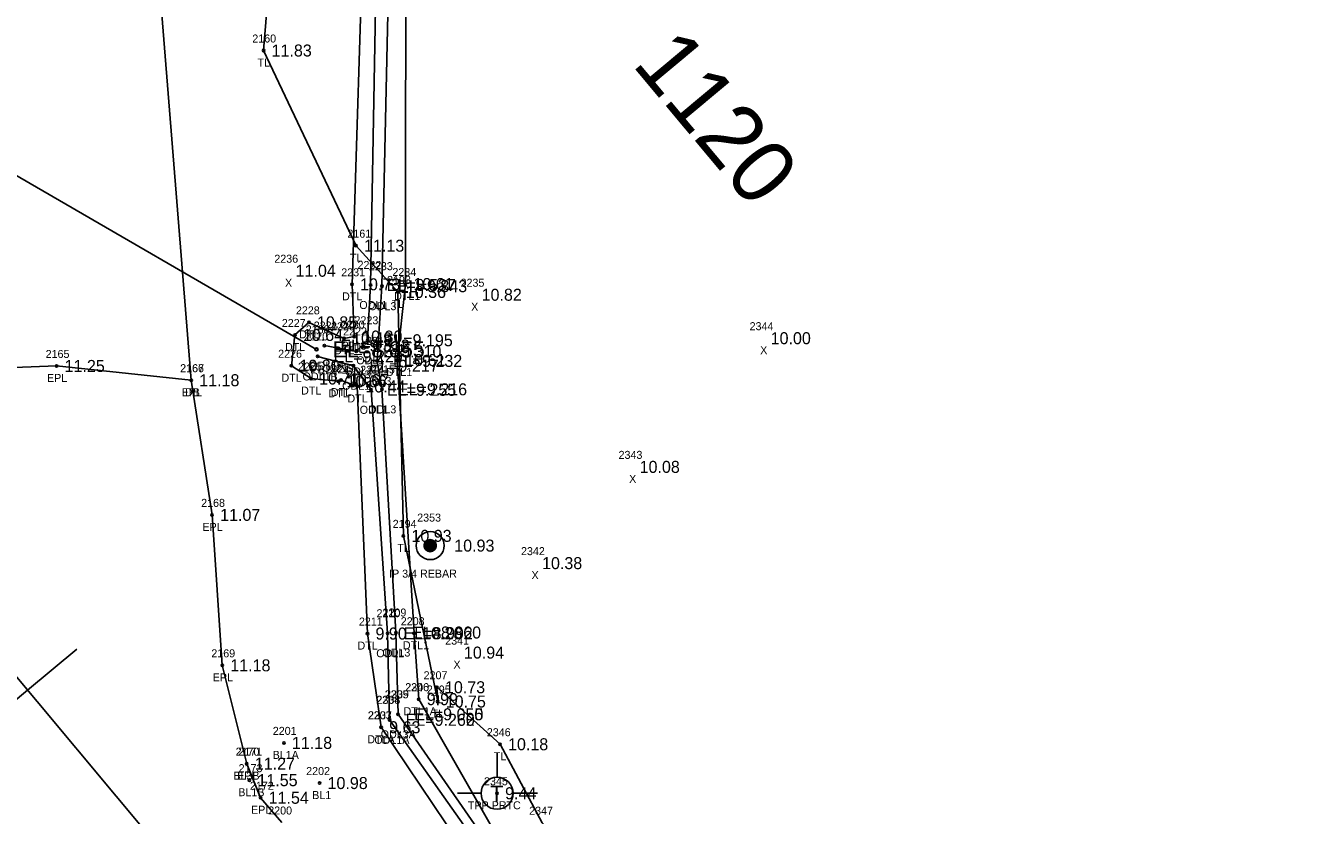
# Model space of a CAD drawing. Extents: x 2042117 to 2045853, y 303080 to 309569.
# Drawn here: x 2044366.1 to 2044524.3, y 304811.9 to 304910.7 of the extents above; entities that cross this region are included whole.
import ezdxf

# ---------------------------------------------------------------- set-up
doc = ezdxf.new("R2010")
doc.units = 0
for name, color, linetype in [('RD_DTM_BkLn_txCode', 7, 'Continuous'), ('RD_EX_DR_Pipe', 7, 'Continuous'), ('RD_EX_DR_Pipe_txCode', 7, 'Continuous'), ('RD_EX_Driveway', 7, 'Continuous'), ('RD_EX_Driveway_txCode', 7, 'Continuous'), ('RD_EX_DV_Prop_txCode', 7, 'Continuous'), ('RD_EX_DV_PropPin', 7, 'Continuous'), ('RD_EX_H2O', 7, 'Continuous'), ('RD_EX_H2O_txCode', 7, 'Continuous'), ('RD_EX_Misc_txCode', 7, 'Continuous'), ('RD_EX_Road', 7, 'Continuous'), ('RD_EX_Road_txCode', 7, 'Continuous'), ('RD_EX_TX_Driveway_ELEV', 7, 'Continuous'), ('RD_EX_TX_DV_Prop_ELEV', 7, 'Continuous'), ('RD_EX_TX_H2O_ELEV', 7, 'Continuous'), ('RD_EX_TX_Misc_ELEV', 7, 'Continuous'), ('RD_EX_TX_Road_ELEV', 7, 'Continuous'), ('RD_EX_TX_UT_ELEV', 7, 'Continuous'), ('RD_EX_TX_VEG_ELEV', 7, 'Continuous'), ('RD_EX_UT', 7, 'Continuous'), ('RD_EX_UT_txCode', 7, 'Continuous'), ('RD_EX_VEG', 7, 'Continuous'), ('RD_EX_VEG_txCode', 7, 'Continuous'), ('RD_HC_Cl', 7, 'Continuous'), ('RD_HC_Data_Tic', 7, 'Continuous'), ('RD_HC_TX_Sta50', 7, 'Continuous'), ('RD_SMD_Locator', 7, 'Continuous'), ('RD_TX_Pipe_ElevEX', 7, 'Continuous')]:
    doc.layers.add(name, color=color, linetype=linetype)

msp = doc.modelspace()

# ---------------------------------------------------------------- linework, layer by layer
at = {"layer": 'RD_EX_DR_Pipe'}
msp.add_line((2044346.71, 304902.5), (2044402.48, 304870.21), dxfattribs=at)
at = {"layer": 'RD_EX_Driveway'}
msp.add_lwpolyline([(2044375.76, 304998.28), (2044380.01, 304949.11), (2044381.7, 304930.26), (2044386.83, 304866.36)], dxfattribs=at)
at = {"layer": 'RD_EX_DV_PropPin'}
for p, q in [((2044415.95, 304845.5), (2044415.95, 304845.89)), ((2044415.99, 304845.4), (2044415.99, 304845.99)), ((2044416.02, 304845.32), (2044416.02, 304846.06)), ((2044416.06, 304845.27), (2044416.06, 304846.12)), ((2044416.09, 304845.22), (2044416.09, 304846.17)), ((2044416.13, 304845.18), (2044416.13, 304846.21)), ((2044416.16, 304845.14), (2044416.16, 304846.24)), ((2044416.2, 304845.11), (2044416.2, 304846.28)), ((2044416.23, 304845.08), (2044416.23, 304846.3)), ((2044416.27, 304845.06), (2044416.27, 304846.33)), ((2044416.3, 304845.04), (2044416.3, 304846.35)), ((2044416.34, 304845.02), (2044416.34, 304846.37)), ((2044416.37, 304845), (2044416.37, 304846.39)), ((2044416.41, 304844.99), (2044416.41, 304846.4)), ((2044416.44, 304844.97), (2044416.44, 304846.41)), ((2044416.48, 304844.96), (2044416.48, 304846.43)), ((2044416.51, 304844.95), (2044416.51, 304846.43)), ((2044416.55, 304844.95), (2044416.55, 304846.44)), ((2044416.58, 304844.94), (2044416.58, 304846.45)), ((2044416.62, 304844.94), (2044416.62, 304846.45)), ((2044416.65, 304844.93), (2044416.65, 304846.45)), ((2044416.69, 304844.93), (2044416.69, 304846.46)), ((2044416.72, 304844.93), (2044416.72, 304846.45)), ((2044416.76, 304844.94), (2044416.76, 304846.45)), ((2044416.79, 304844.94), (2044416.79, 304846.45)), ((2044416.83, 304844.95), (2044416.83, 304846.44)), ((2044416.86, 304844.95), (2044416.86, 304846.43)), ((2044416.9, 304844.96), (2044416.9, 304846.43)), ((2044416.93, 304844.97), (2044416.93, 304846.41)), ((2044416.97, 304844.99), (2044416.97, 304846.4)), ((2044417, 304845), (2044417, 304846.39)), ((2044417.04, 304845.02), (2044417.04, 304846.37)), ((2044417.07, 304845.04), (2044417.07, 304846.35)), ((2044417.11, 304845.06), (2044417.11, 304846.33)), ((2044417.14, 304845.08), (2044417.14, 304846.3)), ((2044417.18, 304845.11), (2044417.18, 304846.28)), ((2044417.21, 304845.14), (2044417.21, 304846.24)), ((2044417.25, 304845.18), (2044417.25, 304846.21)), ((2044417.28, 304845.22), (2044417.28, 304846.17)), ((2044417.32, 304845.27), (2044417.32, 304846.12)), ((2044417.35, 304845.32), (2044417.35, 304846.06)), ((2044417.39, 304845.4), (2044417.39, 304845.99)), ((2044417.42, 304845.5), (2044417.42, 304845.89))]:
    msp.add_line(p, q, dxfattribs=at)
for radius in [1.75, 0.761]:
    msp.add_circle((2044416.69, 304845.69), radius, dxfattribs=at)
at = {"layer": 'RD_EX_H2O'}
for points in [[(2044403.47, 304870.69), (2044407.44, 304869.96), (2044408.86, 304871.35), (2044409.24, 304878.26), (2044410.13, 304929), (2044410.94, 304977.69), (2044415.72, 305077.93), (2044415.23, 305082.87), (2044413.63, 305085.18), (2044400.37, 305083.8), (2044376.8, 305083.33)], [(2044412.68, 304824.61), (2044412.4, 304834.83), (2044410.65, 304865.22), (2044410.04, 304868.77), (2044410.66, 304878.11), (2044411.75, 304929.17), (2044412.06, 304977.88), (2044417.16, 305077.8), (2044420.35, 305084.11), (2044441.54, 305085.32)], [(2044415.25, 304826.5), (2044414.68, 304834.74), (2044412.57, 304868.88), (2044413.59, 304878.38), (2044413.66, 304929.44), (2044414.3, 304978.48), (2044418.39, 305077.45), (2044423.01, 305082.15), (2044441.95, 305081.13)], [(2044410.56, 304822.99), (2044408.85, 304834.7), (2044407.58, 304865.58), (2044405.53, 304866.37), (2044405.23, 304866.22), (2044401.8, 304866.57), (2044399.35, 304868.17), (2044399.78, 304872.01), (2044401.54, 304873.59), (2044405.93, 304871.59), (2044407.19, 304871.81), (2044406.92, 304878.34), (2044408.47, 304927.6)], [(2044415.25, 304826.5), (2044425.66, 304808.25), (2044476.98, 304747.65), (2044539.62, 304670.39), (2044605.13, 304591.24), (2044669.3, 304516.3), (2044710.53, 304469.32), (2044713.85, 304468.76), (2044716.6, 304472.63), (2044721.53, 304481.66), (2044732.23, 304519.55), (2044759.21, 304613.29), (2044789.62, 304712.59), (2044819.6, 304810.16), (2044847.46, 304908.11)], [(2044411.61, 304823.92), (2044411.36, 304834.74), (2044409.29, 304865.16), (2044407.1, 304868.17), (2044402.62, 304869.33)], [(2044411.61, 304823.92), (2044423.39, 304807.22), (2044471.39, 304742.74), (2044536.14, 304667.19), (2044602.88, 304589.74), (2044667.18, 304514.78), (2044710.55, 304465.6), (2044713.57, 304459.34), (2044715.66, 304454.88)], [(2044412.68, 304824.61), (2044424.35, 304807.8), (2044474.04, 304744.84), (2044537.22, 304668.23), (2044604.12, 304590.58), (2044668.25, 304515.54), (2044711.53, 304466.18), (2044714.74, 304463.76), (2044717.49, 304460.61)], [(2044410.56, 304822.99), (2044421.91, 304806.08), (2044470.67, 304741.87), (2044535.46, 304666.28), (2044602.12, 304589.07), (2044666.31, 304514.2), (2044707.72, 304463.54), (2044711.05, 304453.94), (2044714.6, 304446.34)]]:
    msp.add_lwpolyline(points, dxfattribs=at)
at = {"layer": 'RD_EX_Road'}
msp.add_lwpolyline([(2043821.87, 305499.1), (2043885.81, 305423.07), (2043949.56, 305345.93), (2044013.41, 305270.34), (2044077.97, 305194.15), (2044141.4, 305117.67), (2044205.92, 305040.83), (2044269.54, 304964.65), (2044331.73, 304891.04), (2044335.22, 304889.2), (2044346.01, 304875.31), (2044356.18, 304867.61), (2044370.01, 304868.14), (2044386.83, 304866.36), (2044389.44, 304849.53), (2044390.71, 304830.73), (2044393.77, 304818.44), (2044395.5, 304814.18), (2044398.16, 304811.09)], dxfattribs=at)
at = {"layer": 'RD_EX_UT'}
for p, q in [((2044425.04, 304819.81), (2044425.04, 304816.74)), ((2044420.11, 304814.76), (2044423.04, 304814.76)), ((2044427.04, 304814.76), (2044430.11, 304814.76))]:
    msp.add_line(p, q, dxfattribs=at)
msp.add_circle((2044425.04, 304814.74), 2, dxfattribs=at)
at = {"layer": 'RD_EX_VEG'}
msp.add_lwpolyline([(2044387.58, 304996.88), (2044390.53, 304961.86), (2044388.93, 304944.71), (2044397.82, 304931.38), (2044395.87, 304907.56), (2044407.42, 304883.17), (2044412.64, 304877.39), (2044413.34, 304846.91), (2044417.62, 304826.21), (2044417.53, 304827.99), (2044425.41, 304820.87), (2044430.68, 304811.06), (2044486.4, 304757.95), (2044546.53, 304677.07), (2044611.02, 304596.16), (2044662.5, 304521.9), (2044713.91, 304454.08), (2044725.96, 304441.86), (2044733.75, 304433.55)], dxfattribs=at)
at = {"layer": 'RD_HC_Cl'}
msp.add_line((2043284.3, 306123.24), (2045221.31, 303804), dxfattribs=at)
at = {"layer": 'RD_HC_Data_Tic'}
for q in [(2044372.52, 304832.76), (2044360.24, 304822.5)]:
    msp.add_line((2044366.38, 304827.63), q, dxfattribs=at)
at = {"layer": 'RD_SMD_Locator'}
for centre, radius in [((2044395.87, 304907.56), 0.15), ((2044407.42, 304883.17), 0.15), ((2044406.92, 304878.34), 0.15), ((2044409.24, 304878.26), 0.15), ((2044410.66, 304878.11), 0.15), ((2044412.64, 304877.39), 0.15), ((2044413.59, 304878.38), 0.15), ((2044401.54, 304873.59), 0.15), ((2044399.78, 304872.01), 0.15), ((2044405.93, 304871.59), 0.15), ((2044407.19, 304871.81), 0.15), ((2044408.86, 304871.35), 0.15), ((2044402.48, 304870.21), 0.2), ((2044403.47, 304870.69), 0.15), ((2044407.44, 304869.96), 0.15), ((2044370.01, 304868.14), 0.15), ((2044399.35, 304868.17), 0.15), ((2044402.62, 304869.33), 0.15), ((2044407.1, 304868.17), 0.15), ((2044410.04, 304868.77), 0.15), ((2044412.57, 304868.88), 0.15), ((2044386.83, 304866.36), 0.15), ((2044386.83, 304866.36), 0.15), ((2044401.8, 304866.57), 0.15), ((2044405.53, 304866.37), 0.15), ((2044405.23, 304866.22), 0.15), ((2044407.58, 304865.58), 0.15), ((2044409.29, 304865.16), 0.15), ((2044410.65, 304865.22), 0.15), ((2044389.44, 304849.53), 0.15), ((2044413.34, 304846.91), 0.15), ((2044416.69, 304845.69), 0.15), ((2044408.85, 304834.7), 0.15), ((2044411.36, 304834.74), 0.15), ((2044412.4, 304834.83), 0.15), ((2044414.68, 304834.74), 0.15), ((2044390.71, 304830.73), 0.15), ((2044417.53, 304827.99), 0.15), ((2044415.25, 304826.5), 0.15), ((2044415.25, 304826.5), 0.15), ((2044417.62, 304826.21), 0.15), ((2044411.61, 304823.92), 0.15), ((2044411.61, 304823.92), 0.15), ((2044412.68, 304824.61), 0.15), ((2044412.68, 304824.61), 0.15), ((2044410.56, 304822.99), 0.15), ((2044410.56, 304822.99), 0.15), ((2044398.41, 304821.04), 0.15), ((2044425.41, 304820.87), 0.15), ((2044393.77, 304818.44), 0.15), ((2044393.77, 304818.44), 0.15), ((2044394.1, 304816.38), 0.15), ((2044402.86, 304816.02), 0.15), ((2044395.5, 304814.18), 0.15), ((2044425.04, 304814.74), 0.15)]:
    msp.add_circle(centre, radius, dxfattribs=at)

# ---------------------------------------------------------------- texts
at = {"layer": 'RD_DTM_BkLn_txCode'}
for s, p in [('2201', (2044397.02, 304822.04)), ('2171', (2044392.71, 304819.44)), ('BL1A', (2044397, 304819.04)), ('BL3B', (2044392.09, 304816.44)), ('2173', (2044392.75, 304817.38)), ('2202', (2044401.19, 304817.02)), ('BL1B', (2044392.71, 304814.38)), ('BL1', (2044401.94, 304814.02))]:
    msp.add_text(s, height=1, dxfattribs=at).set_placement(p)
at = {"layer": 'RD_EX_DR_Pipe_txCode'}
for s, p in [('2188', (2044401.14, 304872.21)), ('PB', (2044401.7, 304867.21))]:
    msp.add_text(s, height=1, dxfattribs=at).set_placement(p)
at = {"layer": 'RD_EX_Driveway_txCode'}
for s, p in [('2167', (2044385.46, 304867.36)), ('DB', (2044386.05, 304864.36))]:
    msp.add_text(s, height=1, dxfattribs=at).set_placement(p)
at = {"layer": 'RD_EX_DV_Prop_txCode'}
for s, p in [('2353', (2044415.06, 304848.69)), ('IP 3/4 REBAR', (2044411.55, 304841.69))]:
    msp.add_text(s, height=1, dxfattribs=at).set_placement(p)
at = {"layer": 'RD_EX_H2O_txCode'}
for s, p in [('2232', (2044407.61, 304880.26)), ('2233', (2044409.03, 304880.11)), ('2231', (2044405.57, 304879.34)), ('2234', (2044411.96, 304879.38)), ('DTL', (2044405.67, 304876.34)), ('ODL1', (2044407.83, 304875.26)), ('ODL3', (2044408.97, 304875.11)), ('DTL1', (2044412.18, 304876.38)), ('2228', (2044399.91, 304874.59)), ('2223', (2044407.23, 304873.35)), ('2227', (2044398.15, 304873.01)), ('2221', (2044402.13, 304872.69)), ('2229', (2044404.3, 304872.59)), ('2230', (2044405.52, 304872.81)), ('2222', (2044405.81, 304871.96)), ('DTL', (2044400.3, 304871.59)), ('2220', (2044400.95, 304871.33)), ('2218', (2044405.76, 304870.17)), ('2216', (2044408.67, 304870.77)), ('2226', (2044397.69, 304869.17)), ('DTL', (2044398.54, 304870.01)), ('DTL', (2044404.68, 304869.59)), ('DTL', (2044405.95, 304869.81)), ('2217', (2044411.22, 304869.88)), ('2225', (2044400.17, 304867.57)), ('ODL1A', (2044401.58, 304867.69)), ('2224', (2044403.6, 304867.22)), ('2219', (2044404.18, 304867.37)), ('ODL1', (2044407.45, 304868.35)), ('2214', (2044407.94, 304867.16)), ('2215', (2044409.3, 304867.22)), ('DTL', (2044398.1, 304866.17)), ('ODL1B', (2044400.74, 304866.33)), ('ODL1', (2044406.03, 304866.96)), ('2213', (2044406.24, 304866.58)), ('ODL3', (2044408.34, 304865.77)), ('DTL1', (2044411.16, 304866.88)), ('DTL', (2044400.55, 304864.57)), ('DTL', (2044403.98, 304864.22)), ('DTL', (2044404.28, 304864.37)), ('ODL1', (2044405.69, 304865.17)), ('DTL', (2044406.34, 304863.58)), ('ODL1', (2044407.88, 304862.16)), ('ODL3', (2044408.95, 304862.22)), ('2211', (2044407.78, 304835.7)), ('2210', (2044409.98, 304836.74)), ('2209', (2044410.73, 304836.83)), ('2208', (2044413.01, 304835.74)), ('DTL', (2044407.6, 304832.7)), ('DTL1', (2044413.27, 304832.74)), ('ODL1', (2044409.95, 304831.74)), ('ODL3', (2044410.71, 304831.83)), ('2206', (2044413.56, 304827.5)), ('2340', (2044413.58, 304827.5)), ('2204', (2044409.94, 304825.92)), ('2338', (2044409.98, 304825.92)), ('2205', (2044411.01, 304826.61)), ('2339', (2044411.05, 304826.61)), ('DTL1A', (2044413.35, 304824.5)), ('DTL1A', (2044413.35, 304824.5)), ('2203', (2044408.89, 304823.99)), ('2337', (2044408.93, 304823.99)), ('ODL3A', (2044410.5, 304821.61)), ('ODL3A', (2044410.5, 304821.61)), ('DTLA', (2044408.83, 304820.99)), ('DTLA', (2044408.83, 304820.99)), ('ODL1A', (2044409.71, 304820.92)), ('ODL1A', (2044409.71, 304820.92))]:
    msp.add_text(s, height=1, dxfattribs=at).set_placement(p)
at = {"layer": 'RD_EX_Misc_txCode'}
for s, p in [('2236', (2044397.21, 304881.04)), ('X', (2044398.55, 304878.04)), ('2235', (2044420.48, 304878.04)), ('X', (2044421.8, 304875.04)), ('2344', (2044456.59, 304872.61)), ('X', (2044457.91, 304869.61)), ('2343', (2044440.22, 304856.53)), ('X', (2044441.54, 304853.53)), ('2342', (2044428.03, 304844.5)), ('X', (2044429.34, 304841.5)), ('2341', (2044418.56, 304833.32)), ('X', (2044419.59, 304830.32))]:
    msp.add_text(s, height=1, dxfattribs=at).set_placement(p)
at = {"layer": 'RD_EX_Road_txCode'}
for s, p in [('2165', (2044368.64, 304869.14)), ('2166', (2044385.44, 304867.36)), ('EPL', (2044368.81, 304866.14)), ('EPL', (2044385.63, 304864.36)), ('2168', (2044388.07, 304850.53)), ('EPL', (2044388.23, 304847.53)), ('2169', (2044389.34, 304831.73)), ('EPL', (2044389.51, 304828.73)), ('2170', (2044392.38, 304819.44)), ('EPL', (2044392.56, 304816.44)), ('2172', (2044394.16, 304815.18)), ('EPL', (2044394.3, 304812.18)), ('2200', (2044396.45, 304812.09))]:
    msp.add_text(s, height=1, dxfattribs=at).set_placement(p)
at = {"layer": 'RD_EX_TX_Driveway_ELEV'}
msp.add_text('11.18', height=1.5, dxfattribs=at).set_placement((2044387.83, 304865.61))
at = {"layer": 'RD_EX_TX_DV_Prop_ELEV'}
msp.add_text('10.93', height=1.5, dxfattribs=at).set_placement((2044419.69, 304844.94))
at = {"layer": 'RD_EX_TX_H2O_ELEV'}
for s, p in [('10.73', (2044407.92, 304877.59)), ('10.61', (2044414.59, 304877.63)), ('EL=9.537', (2044411.24, 304877.51)), ('EL=9.343', (2044412.66, 304877.36)), ('10.85', (2044402.54, 304872.84)), ('10.64', (2044400.78, 304871.26)), ('EL=9.312', (2044405.47, 304869.94)), ('10.49', (2044406.93, 304870.84)), ('10.30', (2044408.19, 304871.06)), ('EL=9.195', (2044410.86, 304870.6)), ('EL=9.229', (2044404.62, 304868.58)), ('EL=9.310', (2044409.44, 304869.21)), ('10.61', (2044413.57, 304868.13)), ('10.80', (2044400.35, 304867.42)), ('EL=9.217', (2044409.1, 304867.42)), ('EL=9.232', (2044412.04, 304868.02)), ('10.71', (2044402.8, 304865.82)), ('10.66', (2044406.23, 304865.47)), ('10.67', (2044406.53, 304865.62)), ('10.44', (2044408.58, 304864.83)), ('EL=9.255', (2044411.29, 304864.41)), ('EL=9.216', (2044412.65, 304864.47)), ('9.90', (2044409.85, 304833.95)), ('EL=8.992', (2044413.36, 304833.99)), ('EL=8.860', (2044414.4, 304834.08)), ('10.26', (2044415.68, 304833.99)), ('9.99', (2044416.25, 304825.75)), ('9.99', (2044416.25, 304825.75)), ('EL=9.055', (2044414.68, 304823.86)), ('EL=9.050', (2044414.68, 304823.86)), ('9.63', (2044411.56, 304822.24)), ('9.63', (2044411.56, 304822.24)), ('EL=9.262', (2044413.61, 304823.17)), ('EL=9.260', (2044413.61, 304823.17))]:
    msp.add_text(s, height=1.5, dxfattribs=at).set_placement(p)
at = {"layer": 'RD_EX_TX_Misc_ELEV'}
for s, p in [('11.04', (2044399.87, 304879.29)), ('10.82', (2044423.11, 304876.29)), ('10.00', (2044459.22, 304870.86)), ('10.08', (2044442.85, 304854.78)), ('10.38', (2044430.66, 304842.75)), ('10.94', (2044420.9, 304831.57)), ('11.18', (2044399.41, 304820.29)), ('11.27', (2044394.77, 304817.69)), ('11.55', (2044395.1, 304815.63)), ('10.98', (2044403.86, 304815.27))]:
    msp.add_text(s, height=1.5, dxfattribs=at).set_placement(p)
at = {"layer": 'RD_EX_TX_Road_ELEV'}
for s, p in [('11.25', (2044371.01, 304867.39)), ('11.18', (2044387.83, 304865.61)), ('11.07', (2044390.44, 304848.78)), ('11.18', (2044391.71, 304829.98)), ('11.27', (2044394.77, 304817.69)), ('11.54', (2044396.5, 304813.43))]:
    msp.add_text(s, height=1.5, dxfattribs=at).set_placement(p)
at = {"layer": 'RD_EX_TX_UT_ELEV'}
msp.add_text('9.44', height=1.5, dxfattribs=at).set_placement((2044426.04, 304813.99))
at = {"layer": 'RD_EX_TX_VEG_ELEV'}
for s, p in [('11.83', (2044396.87, 304906.81)), ('11.13', (2044408.42, 304882.42)), ('10.36', (2044413.64, 304876.64)), ('10.93', (2044414.34, 304846.16)), ('10.73', (2044418.53, 304827.24)), ('10.75', (2044418.62, 304825.46)), ('10.18', (2044426.41, 304820.12))]:
    msp.add_text(s, height=1.5, dxfattribs=at).set_placement(p)
at = {"layer": 'RD_EX_UT'}
msp.add_text('T', height=2, dxfattribs=at).set_placement((2044424.19, 304813.69))
at = {"layer": 'RD_EX_UT_txCode'}
for s, p in [('2345', (2044423.41, 304815.74)), ('TPP PRTC', (2044421.39, 304812.74))]:
    msp.add_text(s, height=1, dxfattribs=at).set_placement(p)
at = {"layer": 'RD_EX_VEG_txCode'}
for s, p in [('2160', (2044394.46, 304908.56)), ('TL', (2044395.1, 304905.56)), ('2161', (2044406.34, 304884.17)), ('TL', (2044406.65, 304881.17)), ('2193', (2044411.3, 304878.39)), ('TL', (2044411.87, 304875.39)), ('2194', (2044412, 304847.91)), ('TL', (2044412.57, 304844.91)), ('2207', (2044415.86, 304828.99)), ('2195', (2044416.27, 304827.21)), ('TL', (2044416.75, 304825.99)), ('TL', (2044416.85, 304824.21)), ('2346', (2044423.76, 304821.87)), ('TL', (2044424.64, 304818.87)), ('2347', (2044429.05, 304812.06))]:
    msp.add_text(s, height=1, dxfattribs=at).set_placement(p)
at = {"layer": 'RD_HC_TX_Sta50'}
msp.add_text('1120', height=8, rotation=309.8684, dxfattribs=at).set_placement((2044441.79, 304905.82))
at = {"layer": 'RD_TX_Pipe_ElevEX'}
msp.add_text('EL=8.855', height=2, dxfattribs=at).set_placement((2044404.48, 304869.21))

doc.saveas('drawing.dxf')
